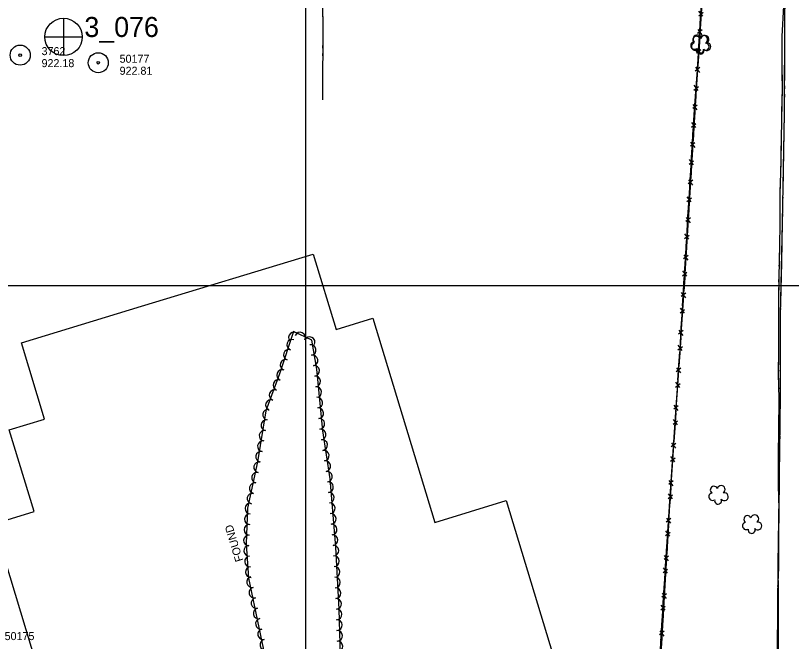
# Model space of a CAD drawing. Extents: x 353423 to 364002, y 127000 to 201942.
# Drawn here: x 360783 to 361364, y 131233 to 131702 of the extents above; entities that cross this region are included whole.
import ezdxf

# ---------------------------------------------------------------- set-up
doc = ezdxf.new("R2010")
doc.units = 0
for name, color, linetype in [('E_DTM_SlopeBottom', 7, 'Continuous'), ('E_FEN_Generic', 7, 'Continuous'), ('E_LAND_TreeLine', 7, 'Continuous'), ('E_RDWY_AsphConc', 7, 'Continuous'), ('E_RDWY_Gravel', 7, 'Continuous'), ('E_STRUCT_WingWall', 7, 'Continuous'), ('E_WTR_FlowLine', 7, 'Continuous')]:
    doc.layers.add(name, color=color, linetype=linetype)

msp = doc.modelspace()

# ---------------------------------------------------------------- linework, layer by layer
at = {"layer": 'E_DTM_SlopeBottom'}
for p, q in [((361294.52, 131702.05), (361297.85, 131704.65)), ((361297.74, 131701.68), (361294.73, 131705.59)), ((361297.14, 131691.4), (361293.75, 131688.79)), ((361293.88, 131691.79), (361296.9, 131687.82)), ((361292.85, 131674.24), (361296.18, 131676.84)), ((361296.08, 131673.87), (361293.06, 131677.78)), ((361295.29, 131663.26), (361291.9, 131660.65)), ((361292.03, 131663.65), (361295.05, 131659.68)), ((361290.99, 131646.46), (361294.36, 131649.02)), ((361294.21, 131646.05), (361291.25, 131650)), ((361293.47, 131635.13), (361290.1, 131632.5)), ((361290.21, 131635.5), (361293.25, 131631.55)), ((361289.09, 131618.64), (361292.42, 131621.25)), ((361292.31, 131618.28), (361289.3, 131622.19)), ((361291.75, 131606.98), (361288.37, 131604.35)), ((361288.48, 131607.35), (361291.53, 131603.4)), ((361287.42, 131590.83), (361290.75, 131593.44)), ((361290.64, 131590.47), (361287.63, 131594.38)), ((361290.02, 131578.83), (361286.64, 131576.21)), ((361286.76, 131579.21), (361289.8, 131575.25)), ((361288.94, 131562.66), (361285.94, 131566.57)), ((361285.72, 131563.03), (361289.06, 131565.62)), ((361288.29, 131550.69), (361284.92, 131548.06)), ((361285.03, 131551.06), (361288.08, 131547.1)), ((361283.98, 131535.22), (361287.31, 131537.82)), ((361287.2, 131534.86), (361284.19, 131538.76)), ((361286.57, 131522.54), (361283.19, 131519.91)), ((361283.31, 131522.91), (361286.35, 131518.96)), ((361282.32, 131507.41), (361285.65, 131510.01)), ((361285.54, 131507.05), (361282.53, 131510.95)), ((361284.77, 131494.39), (361281.38, 131491.78)), ((361281.51, 131494.78), (361284.53, 131490.81)), ((361280.66, 131479.6), (361284, 131482.2)), ((361283.89, 131479.24), (361280.88, 131483.14)), ((361282.9, 131466.25), (361279.51, 131463.64)), ((361279.64, 131466.64), (361282.66, 131462.67)), ((361279.01, 131451.79), (361282.34, 131454.39)), ((361282.23, 131451.43), (361279.22, 131455.33)), ((361277.77, 131438.5), (361280.79, 131434.53)), ((361281.03, 131438.11), (361277.64, 131435.5)), ((361280.39, 131423.62), (361277.4, 131427.54)), ((361277.17, 131424), (361280.52, 131426.58)), ((361279.16, 131409.97), (361275.77, 131407.36)), ((361275.9, 131410.36), (361278.92, 131406.39)), ((361275.34, 131396.2), (361278.68, 131398.78)), ((361278.56, 131395.82), (361275.57, 131399.74)), ((361277.29, 131381.83), (361273.9, 131379.22)), ((361274.03, 131382.22), (361277.05, 131378.25)), ((361273.49, 131368.4), (361276.84, 131370.98)), ((361276.71, 131368.02), (361273.73, 131371.94)), ((361275.42, 131353.7), (361272.03, 131351.08)), ((361272.16, 131354.09), (361275.18, 131350.11)), ((361271.6, 131340.61), (361274.95, 131343.18)), ((361274.82, 131340.22), (361271.84, 131344.15)), ((361273.62, 131325.56), (361270.25, 131322.93)), ((361270.36, 131325.93), (361273.41, 131321.98)), ((361272.93, 131312.42), (361269.95, 131316.35)), ((361269.71, 131312.81), (361273.06, 131315.39)), ((361271.96, 131297.41), (361268.59, 131294.78)), ((361268.69, 131297.78), (361271.74, 131293.83)), ((361267.89, 131285.01), (361271.23, 131287.6)), ((361271.11, 131284.63), (361268.12, 131288.55)), ((361267.03, 131269.63), (361270.08, 131265.68)), ((361270.29, 131269.26), (361266.92, 131266.63)), ((361266.13, 131257.2), (361269.47, 131259.79)), ((361269.35, 131256.83), (361266.35, 131260.74)), ((361268.62, 131241.11), (361265.25, 131238.48)), ((361265.36, 131241.48), (361268.41, 131237.53))]:
    msp.add_line(p, q, dxfattribs=at)
for points in [[(361326.98, 132153.07), (361310.37, 131915.78), (361292.44, 131643.07), (361284.2, 131508.76), (361272.71, 131335.79), (361262.78, 131168.15)], [(361251.44, 130800.37), (361252.63, 130837.63), (361253.85, 130878.52), (361255, 130914.68), (361256.7, 130965.56), (361257.96, 131012.24), (361259.58, 131068.91), (361261.05, 131117.94), (361263.25, 131181.86), (361266.3, 131236.16), (361270.39, 131300.64), (361275.46, 131375.36), (361280.52, 131452.02), (361285.78, 131540.16), (361287.87, 131573.37), (361291.14, 131627.88), (361293.59, 131661.41), (361296.36, 131707.7)], [(361295.34, 131690.69), (361295.93, 131700.63)], [(361296.37, 131702.9), (361295.71, 131692.85)], [(361294.66, 131679.39), (361295.34, 131690.69)], [(361295.28, 131686.2), (361294.52, 131674.76)], [(361293.68, 131662.88), (361294.27, 131672.82)], [(361294.52, 131674.76), (361293.86, 131664.71)], [(361292.87, 131651.59), (361293.59, 131661.41), (361293.68, 131662.88)], [(361293.42, 131658.06), (361292.67, 131646.62)], [(361291.67, 131635.09), (361292.39, 131645.02)], [(361292.67, 131646.62), (361292.44, 131643.07), (361292.04, 131636.57)], [(361290.9, 131623.8), (361291.14, 131627.88), (361291.67, 131635.09)], [(361291.63, 131629.92), (361290.93, 131618.48)], [(361289.91, 131607.29), (361290.5, 131617.23)], [(361290.93, 131618.48), (361290.31, 131608.42)], [(361289.23, 131595.99), (361289.91, 131607.29)], [(361289.91, 131601.77), (361289.21, 131590.33)], [(361289.21, 131590.33), (361288.59, 131580.27)], [(361288.24, 131579.48), (361288.84, 131589.42)], [(361287.55, 131568.18), (361287.87, 131573.37), (361288.24, 131579.48)], [(361288.18, 131573.62), (361287.48, 131562.18)], [(361286.5, 131551.67), (361287.13, 131561.61)], [(361287.48, 131562.18), (361286.86, 131552.12)], [(361285.79, 131540.37), (361286.5, 131551.67)], [(361286.45, 131545.47), (361285.75, 131534.04)], [(361284.8, 131523.86), (361285.4, 131533.8)], [(361285.75, 131534.04), (361285.14, 131523.98)], [(361284.13, 131512.56), (361284.8, 131523.86)], [(361284.73, 131517.33), (361284.2, 131508.76), (361284.01, 131505.89)], [(361283.15, 131496.05), (361283.74, 131505.99)], [(361284.01, 131505.89), (361283.34, 131495.83)], [(361282.47, 131484.75), (361283.15, 131496.05)], [(361282.9, 131489.18), (361282.14, 131477.75)], [(361282.14, 131477.75), (361281.47, 131467.69)], [(361281.49, 131468.24), (361282.08, 131478.18)], [(361280.82, 131456.94), (361281.49, 131468.24)], [(361281.03, 131461.05), (361280.27, 131449.61)], [(361279.76, 131440.44), (361280.41, 131450.37)], [(361280.27, 131449.61), (361279.6, 131439.55)], [(361279.01, 131429.14), (361279.76, 131440.44)], [(361279.16, 131432.91), (361278.4, 131421.47)], [(361278.4, 131421.47), (361277.73, 131411.42)], [(361277.92, 131412.64), (361278.58, 131422.57)], [(361277.18, 131401.34), (361277.92, 131412.64)], [(361277.29, 131404.77), (361276.53, 131393.33)], [(361276.53, 131393.33), (361275.86, 131383.28)], [(361276.09, 131384.84), (361276.74, 131394.77)], [(361275.34, 131373.54), (361275.46, 131375.36), (361276.09, 131384.84)], [(361275.42, 131376.63), (361274.66, 131365.2)], [(361274.66, 131365.2), (361274, 131355.14)], [(361274.22, 131357.04), (361274.89, 131366.98)], [(361273.45, 131345.75), (361274.22, 131357.04)], [(361273.55, 131348.49), (361272.79, 131337.06)], [(361272.79, 131337.06), (361272.71, 131335.79), (361272.19, 131327)], [(361272.33, 131329.25), (361273, 131339.18)], [(361271.56, 131317.95), (361272.33, 131329.25)], [(361271.79, 131320.35), (361271.12, 131308.91)], [(361270.44, 131301.45), (361271.11, 131311.38)], [(361271.12, 131308.91), (361270.52, 131298.85)], [(361269.72, 131290.15), (361270.39, 131300.64), (361270.44, 131301.45)], [(361270.13, 131292.2), (361269.45, 131280.76)], [(361268.68, 131273.65), (361269.3, 131283.58)], [(361269.45, 131280.76), (361268.85, 131270.7)], [(361267.96, 131262.35), (361268.68, 131273.65)], [(361268.46, 131264.05), (361267.78, 131252.61)], [(361266.91, 131245.84), (361267.54, 131255.78)], [(361267.78, 131252.61), (361267.18, 131242.55)], [(361266.21, 131234.54), (361266.3, 131236.16), (361266.91, 131245.84)], [(361266.79, 131235.89), (361266.11, 131224.46)]]:
    msp.add_lwpolyline(points, dxfattribs=at)
at = {"layer": 'E_FEN_Generic'}
msp.add_lwpolyline([(361030.3, 131178.23), (361026.13, 131222.95), (361025.06, 131257.57), (361022.7, 131304.21), (361018.27, 131355.32), (361012.85, 131391.24), (361008.33, 131437.37), (361004.58, 131459.18), (360990.99, 131465.56), (360980.4, 131433.86), (360970.13, 131406.23), (360963.9, 131368.02), (360956.49, 131333.21), (360955.28, 131306.52), (360957.07, 131280.91), (360972.66, 131206.88), (360981.12, 131172.33)], dxfattribs=at)
for centre, radius, start, end in [((361292.89, 131683.92), 2.78, 25.92589, 233.69888), ((361293.33, 131684.68), 2.97, 6.44259, 227.67648), ((361298.25, 131684.32), 2.97, 302.955, 164.18888), ((361299.18, 131684.37), 2.97, 284.09341, 167.06668), ((361291.3, 131679.7), 2.78, 89.41348, 297.18648), ((361291.85, 131678.97), 2.78, 102.60291, 303.61395), ((361295.27, 131676.57), 2.78, 166.0905, 7.10154), ((361295.92, 131675.99), 2.61, 165.31105, 23.24366), ((361299.75, 131678.87), 2.61, 228.79864, 86.73125), ((361300.58, 131678.95), 2.97, 220.60582, 103.57909), ((360991.2, 131461.07), 3.99, 42.40219, 222.38686), ((360995.77, 131461.01), 3.99, 334.86464, 154.84932), ((361002.99, 131457.62), 3.99, 334.86464, 154.84932), ((360989.9, 131455.7), 3.99, 71.53151, 251.51618), ((361003.74, 131451.74), 3.99, 279.77177, 99.75645), ((360987.37, 131448.13), 3.99, 71.53151, 251.51618), ((360984.84, 131440.57), 3.99, 71.53151, 251.51618), ((361005.1, 131443.88), 3.99, 279.77177, 99.75645), ((361006.36, 131436.16), 3.99, 275.59231, 95.57699), ((360982.29, 131432.94), 3.99, 69.61697, 249.60164), ((360979.51, 131425.46), 3.99, 69.61697, 249.60164), ((361007.13, 131428.22), 3.99, 275.59231, 95.57699), ((360976.73, 131417.99), 3.99, 69.61697, 249.60164), ((361007.91, 131420.28), 3.99, 275.59231, 95.57699), ((361008.68, 131412.34), 3.99, 275.59231, 95.57699), ((360973.95, 131410.51), 3.99, 69.61697, 249.60164), ((360971.77, 131403.3), 3.99, 80.74585, 260.73053), ((361009.46, 131404.4), 3.99, 275.59231, 95.57699), ((360970.48, 131395.42), 3.99, 80.74585, 260.73053), ((361010.24, 131396.47), 3.99, 275.59231, 95.57699), ((361011.16, 131388.44), 3.99, 278.60105, 98.58573), ((360969.2, 131387.55), 3.99, 80.74585, 260.73053), ((360967.92, 131379.68), 3.99, 80.74585, 260.73053), ((361012.35, 131380.55), 3.99, 278.60105, 98.58573), ((360966.63, 131371.81), 3.99, 80.74585, 260.73053), ((361013.54, 131372.66), 3.99, 278.60105, 98.58573), ((361014.73, 131364.78), 3.99, 278.60105, 98.58573), ((360965.15, 131363.87), 3.99, 77.99273, 257.97741), ((360963.49, 131356.07), 3.99, 77.99273, 257.97741), ((361015.92, 131356.89), 3.99, 278.60105, 98.58573), ((360961.83, 131348.27), 3.99, 77.99273, 257.97741), ((361016.72, 131349.09), 3.99, 274.95321, 94.93789), ((361305.99, 131346.88), 2.78, 25.92589, 233.69888), ((361311.35, 131347.28), 2.97, 302.955, 164.18888), ((360960.17, 131340.47), 3.99, 77.99273, 257.97741), ((361017.4, 131341.15), 3.99, 274.95321, 94.93789), ((361304.96, 131341.92), 2.78, 102.60291, 303.61395), ((361309.02, 131338.94), 2.61, 165.31105, 23.24366), ((361313.68, 131341.91), 2.97, 220.60582, 103.57909), ((360958.57, 131333.01), 3.99, 87.40938, 267.39406), ((361018.09, 131333.2), 3.99, 274.95321, 94.93789), ((360958.21, 131325.04), 3.99, 87.40938, 267.39406), ((361018.78, 131325.25), 3.99, 274.95321, 94.93789), ((361336.54, 131325.35), 2.97, 302.955, 164.18888), ((361330.14, 131320), 2.78, 102.60291, 303.61395), ((361331.18, 131324.95), 2.78, 25.92589, 233.69888), ((361338.86, 131319.98), 2.97, 220.60582, 103.57909), ((360957.85, 131317.07), 3.99, 87.40938, 267.39406), ((361019.47, 131317.31), 3.99, 274.95321, 94.93789), ((361334.21, 131317.02), 2.61, 165.31105, 23.24366), ((360957.49, 131309.1), 3.99, 87.40938, 267.39406), ((361020.15, 131309.36), 3.99, 274.95321, 94.93789), ((360957.73, 131301.38), 3.99, 94.00712, 273.99179), ((361020.74, 131301.48), 3.99, 272.91547, 92.90014), ((360958.29, 131293.43), 3.99, 94.00712, 273.99179), ((361021.15, 131293.52), 3.99, 272.91547, 92.90014), ((360958.84, 131285.47), 3.99, 94.00712, 273.99179), ((361021.55, 131285.55), 3.99, 272.91547, 92.90014), ((360959.84, 131277.87), 3.99, 101.90447, 281.88915), ((361021.96, 131277.59), 3.99, 272.91547, 92.90014), ((360961.49, 131270.06), 3.99, 101.90447, 281.88915), ((361022.36, 131269.62), 3.99, 272.91547, 92.90014), ((360963.13, 131262.26), 3.99, 101.90447, 281.88915), ((361022.77, 131261.66), 3.99, 272.91547, 92.90014), ((360964.78, 131254.45), 3.99, 101.90447, 281.88915), ((361023.09, 131253.73), 3.99, 271.77132, 91.756), ((360966.42, 131246.65), 3.99, 101.90447, 281.88915), ((361023.34, 131245.76), 3.99, 271.77132, 91.756), ((360968.06, 131238.85), 3.99, 101.90447, 281.88915), ((361023.58, 131237.79), 3.99, 271.77132, 91.756), ((360969.71, 131231.04), 3.99, 101.90447, 281.88915), ((361023.83, 131229.81), 3.99, 271.77132, 91.756)]:
    msp.add_arc(centre, radius, start, end, dxfattribs=at)
at = {"layer": 'E_LAND_TreeLine'}
for p, q in [((361000, 131000), (361000, 133500)), ((360000, 131500), (363500, 131500)), ((360000, 131500), (364000, 131500)), ((361000, 129000), (361000, 131500))]:
    msp.add_line(p, q, dxfattribs=at)
at = {"layer": 'E_RDWY_AsphConc'}
for centre, radius in [((360786.07, 131672.58), 7.5), ((360786.07, 131672.58), 7.5), ((360786.07, 131672.58), 0.96), ((360786.07, 131672.58), 0.96), ((360844.56, 131666.88), 7.5), ((360844.56, 131666.88), 7.5), ((360844.56, 131666.88), 0.96), ((360844.56, 131666.88), 0.96)]:
    msp.add_circle(centre, radius, dxfattribs=at)
at = {"layer": 'E_RDWY_Gravel'}
for p, q in [((360818.47, 131700.25), (360818.4, 131672.4)), ((360818.47, 131700.25), (360818.4, 131672.4)), ((360804.56, 131686.22), (360832.46, 131686.21)), ((360804.56, 131686.22), (360832.46, 131686.21))]:
    msp.add_line(p, q, dxfattribs=at)
msp.add_circle((360818.52, 131686.23), 14, dxfattribs=at)
msp.add_circle((360818.52, 131686.23), 14, dxfattribs=at)
at = {"layer": 'E_STRUCT_WingWall'}
for points in [[(361354.49, 131184.2), (361354.15, 131291.42), (361355.16, 131358.07), (361355.84, 131417.31), (361355.87, 131477.78), (361357.38, 131547.27), (361358.93, 131628.91), (361359.03, 131701.84), (361360.75, 131775.74), (361360.08, 131850.36)], [(361012.75, 131639.04), (361013.06, 131697.76), (361011.68, 131744.21)], [(361013.02, 131689.86), (361013.06, 131697.76), (361012.44, 131718.75)], [(361359.01, 131683.82), (361359.03, 131701.84), (361359.31, 131714.01)], [(361357.97, 131709.58), (361356.94, 131686.46), (361356.76, 131668.09), (361357.02, 131647.85), (361356.57, 131624.25), (361356.25, 131609.23), (361356.05, 131592.59), (361355.45, 131568.45), (361355.22, 131547.3), (361355.03, 131528.76), (361354.46, 131506.64), (361354.38, 131486.16), (361354.44, 131471.12), (361354.44, 131451.82), (361354.19, 131434), (361354.64, 131415.52), (361354.42, 131391.33), (361353.97, 131373.77), (361354.2, 131350.19), (361354.6, 131332.82), (361354.25, 131310.78), (361354.45, 131291.09), (361353.49, 131270), (361353.7, 131250.65), (361353.41, 131233.89), (361353.08, 131219.87)], [(361357.97, 131709.58), (361356.94, 131686.46), (361356.88, 131680.6)], [(361012.99, 131683.88), (361013, 131685.88)], [(361358.97, 131653.64), (361359.01, 131683.82)], [(361012.96, 131677.9), (361012.97, 131679.9)], [(361012.93, 131671.93), (361012.94, 131673.92)], [(361356.84, 131676.6), (361356.82, 131674.6)], [(361012.75, 131639.04), (361012.91, 131667.94)], [(361356.79, 131670.6), (361356.77, 131668.6)], [(361356.8, 131664.6), (361356.83, 131662.6)], [(361356.88, 131658.6), (361357.02, 131647.85), (361356.67, 131629.6)], [(361358.96, 131647.39), (361358.96, 131649.47)], [(361358.95, 131641.14), (361358.95, 131643.23)], [(361358.94, 131634.9), (361358.94, 131636.98)], [(361358.39, 131600.55), (361358.93, 131628.91), (361358.93, 131630.73)], [(361356.67, 131629.6), (361356.57, 131624.25), (361356.25, 131609.23), (361356.15, 131600.61)], [(361356.1, 131596.61), (361356.07, 131594.61)], [(361357.82, 131570.37), (361358.39, 131600.55)], [(361356, 131590.61), (361355.95, 131588.61)], [(361355.85, 131584.61), (361355.8, 131582.61)], [(361355.7, 131578.61), (361355.45, 131568.45), (361355.24, 131549.62)], [(361357.7, 131564.12), (361357.74, 131566.21)], [(361357.58, 131557.88), (361357.62, 131559.96)], [(361355.24, 131549.62), (361355.22, 131547.3), (361355.03, 131528.76), (361354.82, 131520.62)], [(361357.46, 131551.63), (361357.5, 131553.72)], [(361356.73, 131517.29), (361357.38, 131547.27), (361357.38, 131547.47)], [(361354.72, 131516.62), (361354.67, 131514.62)], [(361356.07, 131487.11), (361356.73, 131517.29)], [(361354.57, 131510.62), (361354.51, 131508.62)], [(361354.45, 131504.63), (361354.45, 131502.63)], [(361354.43, 131498.63), (361354.38, 131486.16), (361354.44, 131471.12), (361354.44, 131469.63)], [(361355.94, 131480.86), (361355.98, 131482.95)], [(361355.87, 131474.62), (361355.87, 131476.7)], [(361354.44, 131469.63), (361354.44, 131451.82), (361354.28, 131440.63)], [(361355.87, 131468.37), (361355.87, 131470.45)], [(361355.85, 131434.02), (361355.86, 131464.21)], [(361354.23, 131436.63), (361354.2, 131434.63)], [(361355.69, 131403.83), (361355.84, 131417.31), (361355.85, 131434.02)], [(361354.27, 131430.63), (361354.32, 131428.63)], [(361354.42, 131424.63), (361354.47, 131422.63)], [(361354.56, 131418.63), (361354.64, 131415.52), (361354.42, 131391.33), (361354.38, 131389.64)], [(361355.61, 131397.59), (361355.64, 131399.67)], [(361355.54, 131391.34), (361355.57, 131393.42)], [(361354.38, 131389.64), (361353.97, 131373.77), (361354.1, 131360.64)], [(361355.47, 131385.1), (361355.49, 131387.18)], [(361355.05, 131350.75), (361355.16, 131358.07), (361355.42, 131380.93)], [(361354.14, 131356.64), (361354.16, 131354.64)], [(361354.2, 131350.64), (361354.2, 131350.19), (361354.24, 131348.64)], [(361354.59, 131320.57), (361355.05, 131350.75)], [(361354.33, 131344.64), (361354.38, 131342.64)], [(361354.47, 131338.64), (361354.6, 131332.82), (361354.25, 131310.78), (361354.26, 131309.65)], [(361354.49, 131314.32), (361354.53, 131316.4)], [(361354.26, 131309.65), (361354.45, 131291.09), (361353.97, 131280.66)], [(361354.4, 131308.08), (361354.43, 131310.16)], [(361354.31, 131301.83), (361354.34, 131303.91)], [(361354.22, 131267.48), (361354.15, 131291.42), (361354.24, 131297.67)], [(361353.79, 131276.66), (361353.7, 131274.67)], [(361353.52, 131270.67), (361353.49, 131270), (361353.51, 131268.67)], [(361353.55, 131264.67), (361353.57, 131262.67)], [(361354.32, 131237.29), (361354.22, 131267.48)], [(361353.61, 131258.67), (361353.7, 131250.65), (361353.41, 131233.89), (361353.31, 131229.68)]]:
    msp.add_lwpolyline(points, dxfattribs=at)
at = {"layer": 'E_WTR_FlowLine'}
msp.add_lwpolyline([(361192.3, 131200.74), (360813.79, 131085.81), (360788.43, 131169.36), (360810.47, 131176.05), (360766.28, 131321.65), (360796.45, 131330.81), (360777.88, 131391.99), (360804.31, 131400.01), (360786.97, 131457.15), (360877.05, 131484.49), (361005.73, 131523.55), (361022.85, 131467.16), (361050.29, 131475.48), (361096.72, 131322.49), (361150.2, 131339.09)], close=True, dxfattribs=at)

# ---------------------------------------------------------------- texts
at = {"layer": 'E_RDWY_AsphConc'}
for s, p in [('3762', (360802.07, 131672.58)), ('3762', (360802.07, 131672.58)), ('50177', (360860.56, 131666.88)), ('50177', (360860.56, 131666.88)), ('922.18', (360802.07, 131663.58)), ('922.18', (360802.07, 131663.58)), ('922.81', (360860.56, 131657.88)), ('922.81', (360860.56, 131657.88)), ('50175', (360774.38, 131234.49))]:
    msp.add_text(s, height=6, dxfattribs=at).set_placement(p)
at = {"layer": 'E_RDWY_Gravel'}
msp.add_text('3_076', height=15, dxfattribs=at).set_placement((360834.17, 131686.16))
msp.add_text('3_076', height=15, dxfattribs=at).set_placement((360834.17, 131686.16))
at = {"layer": 'E_WTR_FlowLine'}
msp.add_text('FOUND', height=6, rotation=106.90502, dxfattribs=at).set_placement((360953.28, 131294.19))

doc.saveas('drawing.dxf')
